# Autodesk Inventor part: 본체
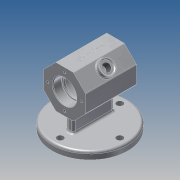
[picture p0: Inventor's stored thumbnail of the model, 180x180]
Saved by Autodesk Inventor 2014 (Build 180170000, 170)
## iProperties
Created: 2021-02
Part Number: 본체
Material: 알루미늄 6061
Document SubType Name: Modeling
Designer: kb542
Density: 2.71 g/cm^3
Appearance: 알루미늄 - 평지
Mass: 558.812 g
Surface Area: 509.677 cm^2
Volume: 206.204 cm^3
Author: kb542
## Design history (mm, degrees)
sketch "스케치1" dims "d0" = 58
  geometry: L1 (12.012, 91)-(29, 74.012); L2 (29, 74.012)-(29, 49.988); L3 (29, 49.988)-(12.012, 33); L4 (12.012, 33)-(-12.012, 33); L5 (-12.012, 33)-(-29, 49.988); L6 (-29, 49.988)-(-29, 74.012); L7 (-29, 74.012)-(-12.012, 91); L8 (-12.012, 91)-(12.012, 91); 4 further points
  constraints: 16 end point, 2 vertical alignment, 1 coincident, 1 horizontal, 1 midpoint, 19 other
  dimensions: "d1" = 62 distance of point (0, 0) point (0, 62)
extrude "돌출1" new body sketch "스케치1" stored distance "d2" = 70; taper "d3" = 0 deg
sketch "스케치2"
  geometry: L1 (91, -35)-(33, -35) reference; L2 (33, -35)-(33, 35) reference; L3 (33, 35)-(91, 35) reference; L4 (91, 35)-(91, -35) reference; L5 (62, 35)-(62, -35); L6 (62, 35)-(78, 35); L7 (78, 35)-(78, 23); L8 (76, 20)-(84, 20); L9 (84, 20)-(84, -20); L10 (84, -20)-(76, -20); L11 (76, -20)-(76, -23); L12 (76, -23)-(78, -23); L13 (78, -23)-(78, -35); L14 (78, -35)-(62, -35); L15 (78, 23)-(76, 23); L16 (76, 23)-(76, 20); 1 further point
  constraints: 24 end point, 6 parallel, 3 perpendicular, 2 midpoint, 2 point on line, 1 collinear
  dimensions: "d4" = 12 distance of L6.end L7.end; "d5" = 40 distance of L8.end L9.end; "d6" = 12 distance of L12.end L13.end; "d8" = 32 diameter of L7 L5; "d9" = 44 diameter of L9 L5; "d11" = 32 diameter of L13 L5; "d12" = 28 diameter of L11 L5; "d13" = 3 distance of L15.end L8.start; "d14" = 28 diameter of L16 L5
revolve "회전1" sketch "스케치2" stored, may be unused: angle "d15" = 90 deg
sketch "스케치3"
  geometry: C1 r 52 at (0, 0); C2 r 4.5 at (41, 0); C3 r 4.5 at (0, -41); C4 r 4.5 at (-41, 0); C5 r 4.5 at (0, 41); A1 r 41 centre (0, 0) between (41, 0) and (0, -41); 1 further point
  constraints: 6 centre point, 4 point on circle, 3 equal radius, 2 coincident, 2 horizontal alignment, 2 vertical alignment
  dimensions: "d16" = 104 diameter of C1; "d17" = 82 diameter of A1; "d18" = 9 diameter of C2
extrude "돌출2" join sketch "스케치3" distance "d19" = 10; taper "d20" = 0 deg
sketch "스케치4"
  geometry: L1 (-5, 28)-(5, 28); L2 (5, 28)-(5, -28); L3 (5, -28)-(-5, -28); L4 (-5, -28)-(-5, 28); C1 r 52 at (0, 0) reference; 2 further points
  constraints: 8 end point, 2 midpoint, 2 parallel, 1 horizontal, 1 horizontal alignment, 1 perpendicular, 1 vertical alignment
  dimensions: "d21" = 10 distance of L1.start L1.end; "d22" = 56 distance of L1.end L2.end
extrude "돌출3" join sketch "스케치4" stored distance "d23" = 10; taper "d24" = 0 deg
sketch "스케치5"
  geometry: L1 (-24.024, 70)-(0, 70) reference; C1 r 10 at (-12.012, 35); 2 further points
  constraints: 1 centre point, 1 midpoint, 1 vertical alignment
  dimensions: "d25" = 35 distance from line of C1.centre L1; "d26" = 20 diameter of C1
extrude "돌출4" join sketch "스케치5" distance "d27" = 5; taper "d28" = 0 deg
hole "구멍1" diameter "d31" = 10.917; stored, may be unused: countersink angle "d35" = 90 deg, drill point angle "d37" = 118 deg; dims "d29" = 10, "d30" = 10, "d32" = 6, "d33" = 16, "d34" = 2, "d36" = 8
sketch "스케치6"
  geometry: C1 r 16 at (0, 62) reference; A1 r 23 centre (0, 62) between (0, 85) and (-23, 62); 3 further points
  constraints: 4 point on circle, 2 horizontal alignment, 2 vertical alignment, 1 centre point
  dimensions: "d42" = 46 diameter of A1
hole "구멍2" sketch "스케치6" at (0, 85), (-23, 62), (23, 62), (0, 39) diameter "d43" = 3.242; stored, may be unused: countersink angle "d47" = 90 deg, drill point angle "d49" = 118 deg; dims "d44" = 8, "d45" = 16, "d46" = 2, "d48" = 10
sketch "스케치8"
  geometry: L1 (24.024, 0)-(0, 0) reference; L2 (-16.988, 0)-(-16.988, 70) reference; 2 further points
  constraints: 1 other
  dimensions: "d51" = 29 distance from line of L2 point (12.012, 35); "d52" = 35 distance from line of L1 point (12.012, 35)
feature "엠보싱1" sketch "스케치8" dims "d0" = 58, "d1" = 62, "d4" = 12, "d5" = 40, "d6" = 12, "d8" = 32, "d9" = 44, "d11" = 32, "d12" = 28, "d13" = 3, "d14" = 28, "d53" = 0.5, "d54" = 0
fillet "모깎기1" dims "d38" = 0.3, "d39" = 1, "d40" = 3
fillet "모깎기2" dims "d41" = 3
chamfer "모따기1" distance "d55" = 1; stored, may be unused: second distance "d56" = 2, angle "d57" = 45 deg
node "솔리드1"
mirror "대칭1"
node "절단 모서리 투영1"
